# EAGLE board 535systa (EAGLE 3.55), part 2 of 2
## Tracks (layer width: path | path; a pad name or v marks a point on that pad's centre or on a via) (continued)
N$460  (via drill 0.81 pad 1.93)
  other vias: 22.52,77.93
N$461  (via drill 0.81 pad 1.93)
  other vias: 22.52,75.07
N$462  (via drill 0.81 pad 1.93)
  other vias: 22.52,72.21
N$463  (via drill 0.81 pad 1.93)
  other vias: 22.52,69.35
N$464  (via drill 0.81 pad 1.93)
  other vias: 22.52,66.5
N$465  (via drill 0.81 pad 1.93)
  other vias: 22.52,63.64
N$466  (via drill 0.81 pad 1.93)
  other vias: 22.52,60.78
N$467  (via drill 0.81 pad 1.93)
  other vias: 22.52,57.92
N$468  (via drill 0.81 pad 1.93)
  other vias: 22.52,55.07
N$469  (via drill 0.81 pad 1.93)
  other vias: 22.52,52.21
N$470  (via drill 0.81 pad 1.93)
  other vias: 22.52,49.35
N$471  (via drill 0.81 pad 1.93)
  other vias: 22.52,46.49
N$472  (via drill 0.81 pad 1.93)
  other vias: 22.52,43.64
N$473  (via drill 0.81 pad 1.93)
  other vias: 22.52,40.78
N$474  (via drill 0.81 pad 1.93)
  other vias: 22.52,37.92
N$475  (via drill 0.81 pad 1.93)
  other vias: 22.52,35.06
N$476  (via drill 0.81 pad 1.93)
  other vias: 22.52,32.21
N$477  (via drill 0.81 pad 1.93)
  other vias: 22.52,29.35
N$478  (via drill 0.81 pad 1.93)
  other vias: 22.52,26.49
N$479  (via drill 0.81 pad 1.93)
  other vias: 22.52,23.63
N$480  (via drill 0.81 pad 1.93)
  other vias: 22.52,20.78
N$481  (via drill 0.81 pad 1.93)
  other vias: 22.52,17.92
N$482  (via drill 0.81 pad 1.93)
  other vias: 22.52,15.06
N$483  (via drill 0.81 pad 1.93)
  other vias: 22.52,12.2
N$484  (via drill 0.81 pad 1.93)
  other vias: 22.52,9.35
N$485  (via drill 0.81 pad 1.93)
  other vias: 22.52,6.49
N$487  (via drill 0.81 pad 1.93)
  other vias: 19.66,95.07
N$488  (via drill 0.81 pad 1.93)
  other vias: 19.66,92.21
N$489  (via drill 0.81 pad 1.93)
  other vias: 19.66,89.36
N$490  (via drill 0.81 pad 1.93)
  other vias: 19.66,86.5
N$491  (via drill 0.81 pad 1.93)
  other vias: 19.66,83.64
N$492  (via drill 0.81 pad 1.93)
  other vias: 19.66,80.78
N$493  (via drill 0.81 pad 1.93)
  other vias: 19.66,77.93
N$494  (via drill 0.81 pad 1.93)
  other vias: 19.66,75.07
N$495  (via drill 0.81 pad 1.93)
  other vias: 19.66,72.21
N$496  (via drill 0.81 pad 1.93)
  other vias: 19.66,69.35
N$497  (via drill 0.81 pad 1.93)
  other vias: 19.66,66.5
N$498  (via drill 0.81 pad 1.93)
  other vias: 19.66,63.64
N$499  (via drill 0.81 pad 1.93)
  other vias: 19.66,60.78
N$500  (via drill 0.81 pad 1.93)
  other vias: 19.66,57.92
N$501  (via drill 0.81 pad 1.93)
  other vias: 19.66,55.07
N$502  (via drill 0.81 pad 1.93)
  other vias: 19.66,52.21
N$503  (via drill 0.81 pad 1.93)
  other vias: 19.66,49.35
N$504  (via drill 0.81 pad 1.93)
  other vias: 19.66,46.49
N$505  (via drill 0.81 pad 1.93)
  other vias: 19.66,43.64
N$506  (via drill 0.81 pad 1.93)
  other vias: 19.66,40.78
N$507  (via drill 0.81 pad 1.93)
  other vias: 19.66,37.92
N$508  (via drill 0.81 pad 1.93)
  other vias: 19.66,35.06
N$509  (via drill 0.81 pad 1.93)
  other vias: 19.66,32.21
N$510  (via drill 0.81 pad 1.93)
  other vias: 19.66,29.35
N$511  (via drill 0.81 pad 1.93)
  other vias: 19.66,26.49
N$512  (via drill 0.81 pad 1.93)
  other vias: 19.66,23.63
N$513  (via drill 0.81 pad 1.93)
  other vias: 19.66,20.78
N$514  (via drill 0.81 pad 1.93)
  other vias: 19.66,17.92
N$515  (via drill 0.81 pad 1.93)
  other vias: 19.66,15.06
N$516  (via drill 0.81 pad 1.93)
  other vias: 19.66,12.2
N$517  (via drill 0.81 pad 1.93)
  other vias: 19.66,9.35
N$518  (via drill 0.81 pad 1.93)
  other vias: 19.66,6.49
N$520  (via drill 0.81 pad 1.93)
  other vias: 16.8,95.07
N$521  (via drill 0.81 pad 1.93)
  other vias: 16.8,92.21
N$522  (via drill 0.81 pad 1.93)
  other vias: 16.8,89.36
N$523  (via drill 0.81 pad 1.93)
  other vias: 16.8,86.5
N$524  (via drill 0.81 pad 1.93)
  other vias: 16.8,83.64
N$525  (via drill 0.81 pad 1.93)
  other vias: 16.8,80.78
N$526  (via drill 0.81 pad 1.93)
  other vias: 16.8,77.93
N$527  (via drill 0.81 pad 1.93)
  other vias: 16.8,75.07
N$528  (via drill 0.81 pad 1.93)
  other vias: 16.8,72.21
N$529  (via drill 0.81 pad 1.93)
  other vias: 16.8,69.35
N$530  (via drill 0.81 pad 1.93)
  other vias: 16.8,66.5
N$531  (via drill 0.81 pad 1.93)
  other vias: 16.8,63.64
N$532  (via drill 0.81 pad 1.93)
  other vias: 16.8,60.78
N$533  (via drill 0.81 pad 1.93)
  other vias: 16.8,57.92
N$534  (via drill 0.81 pad 1.93)
  other vias: 16.8,55.07
N$535  (via drill 0.81 pad 1.93)
  other vias: 16.8,52.21
N$536  (via drill 0.81 pad 1.93)
  other vias: 16.8,49.35
N$537  (via drill 0.81 pad 1.93)
  other vias: 16.8,46.49
N$538  (via drill 0.81 pad 1.93)
  other vias: 16.8,43.64
N$539  (via drill 0.81 pad 1.93)
  other vias: 16.8,40.78
N$540  (via drill 0.81 pad 1.93)
  other vias: 16.8,37.92
N$541  (via drill 0.81 pad 1.93)
  other vias: 16.8,35.06
N$542  (via drill 0.81 pad 1.93)
  other vias: 16.8,32.21
N$543  (via drill 0.81 pad 1.93)
  other vias: 16.8,29.35
N$544  (via drill 0.81 pad 1.93)
  other vias: 16.8,26.49
N$545  (via drill 0.81 pad 1.93)
  other vias: 16.8,23.63
N$546  (via drill 0.81 pad 1.93)
  other vias: 16.8,20.78
N$547  (via drill 0.81 pad 1.93)
  other vias: 16.8,17.92
N$548  (via drill 0.81 pad 1.93)
  other vias: 16.8,15.06
N$549  (via drill 0.81 pad 1.93)
  other vias: 16.8,12.2
N$550  (via drill 0.81 pad 1.93)
  other vias: 16.8,9.35
N$551  (via drill 0.81 pad 1.93)
  other vias: 16.8,6.49
N$553  (via drill 0.81 pad 1.93)
  other vias: 13.94,95.07
N$554  (via drill 0.81 pad 1.93)
  other vias: 13.94,92.21
N$555  (via drill 0.81 pad 1.93)
  other vias: 13.94,89.36
N$556  (via drill 0.81 pad 1.93)
  other vias: 13.94,86.5
N$557  (via drill 0.81 pad 1.93)
  other vias: 13.94,83.64
N$558  (via drill 0.81 pad 1.93)
  other vias: 13.94,80.78
N$559  (via drill 0.81 pad 1.93)
  other vias: 13.94,77.93
N$560  (via drill 0.81 pad 1.93)
  other vias: 13.94,75.07
N$561  (via drill 0.81 pad 1.93)
  other vias: 13.94,72.21
N$562  (via drill 0.81 pad 1.93)
  other vias: 13.94,69.35
N$563  (via drill 0.81 pad 1.93)
  other vias: 13.94,66.5
N$564  (via drill 0.81 pad 1.93)
  other vias: 13.94,63.64
N$565  (via drill 0.81 pad 1.93)
  other vias: 13.94,60.78
N$566  (via drill 0.81 pad 1.93)
  other vias: 13.94,57.92
N$567  (via drill 0.81 pad 1.93)
  other vias: 13.94,55.07
N$568  (via drill 0.81 pad 1.93)
  other vias: 13.94,52.21
N$569  (via drill 0.81 pad 1.93)
  other vias: 13.94,49.35
N$570  (via drill 0.81 pad 1.93)
  other vias: 13.94,46.49
N$571  (via drill 0.81 pad 1.93)
  other vias: 13.94,43.64
N$572  (via drill 0.81 pad 1.93)
  other vias: 13.94,40.78
N$573  (via drill 0.81 pad 1.93)
  other vias: 13.94,37.92
N$574  (via drill 0.81 pad 1.93)
  other vias: 13.94,35.06
N$575  (via drill 0.81 pad 1.93)
  other vias: 13.94,32.21
N$576  (via drill 0.81 pad 1.93)
  other vias: 13.94,29.35
N$577  (via drill 0.81 pad 1.93)
  other vias: 13.94,26.49
N$578  (via drill 0.81 pad 1.93)
  other vias: 13.94,23.63
N$579  (via drill 0.81 pad 1.93)
  other vias: 13.94,20.78
N$580  (via drill 0.81 pad 1.93)
  other vias: 13.94,17.92
N$581  (via drill 0.81 pad 1.93)
  other vias: 13.94,15.06
N$582  (via drill 0.81 pad 1.93)
  other vias: 13.94,12.2
N$583  (via drill 0.81 pad 1.93)
  other vias: 13.94,9.35
N$584  (via drill 0.81 pad 1.93)
  other vias: 13.94,6.49
N$586  (via drill 0.81 pad 1.93)
  other vias: 11.09,95.07
N$587  (via drill 0.81 pad 1.93)
  other vias: 11.09,92.21
N$588  (via drill 0.81 pad 1.93)
  other vias: 11.09,89.36
N$589  (via drill 0.81 pad 1.93)
  other vias: 11.09,86.5
N$590  (via drill 0.81 pad 1.93)
  other vias: 11.09,83.64
N$591  (via drill 0.81 pad 1.93)
  other vias: 11.09,80.78
N$592  (via drill 0.81 pad 1.93)
  other vias: 11.09,77.93
N$593  (via drill 0.81 pad 1.93)
  other vias: 11.09,75.07
N$594  (via drill 0.81 pad 1.93)
  other vias: 11.09,72.21
N$595  (via drill 0.81 pad 1.93)
  other vias: 11.09,69.35
N$596  (via drill 0.81 pad 1.93)
  other vias: 11.09,66.5
N$597  (via drill 0.81 pad 1.93)
  other vias: 11.09,63.64
N$598  (via drill 0.81 pad 1.93)
  other vias: 11.09,60.78
N$599  (via drill 0.81 pad 1.93)
  other vias: 11.09,57.92
N$600  (via drill 0.81 pad 1.93)
  other vias: 11.09,55.07
N$601  (via drill 0.81 pad 1.93)
  other vias: 11.09,52.21
N$602  (via drill 0.81 pad 1.93)
  other vias: 11.09,49.35
N$603  (via drill 0.81 pad 1.93)
  other vias: 11.09,46.49
N$604  (via drill 0.81 pad 1.93)
  other vias: 11.09,43.64
N$605  (via drill 0.81 pad 1.93)
  other vias: 11.09,40.78
N$606  (via drill 0.81 pad 1.93)
  other vias: 11.09,37.92
N$607  (via drill 0.81 pad 1.93)
  other vias: 11.09,35.06
N$608  (via drill 0.81 pad 1.93)
  other vias: 11.09,32.21
N$609  (via drill 0.81 pad 1.93)
  other vias: 11.09,29.35
N$610  (via drill 0.81 pad 1.93)
  other vias: 11.09,26.49
N$611  (via drill 0.81 pad 1.93)
  other vias: 11.09,23.63
N$612  (via drill 0.81 pad 1.93)
  other vias: 11.09,20.78
N$613  (via drill 0.81 pad 1.93)
  other vias: 11.09,17.92
N$614  (via drill 0.81 pad 1.93)
  other vias: 11.09,15.06
N$615  (via drill 0.81 pad 1.93)
  other vias: 11.09,12.2
N$616  (via drill 0.81 pad 1.93)
  other vias: 11.09,9.35
N$617  (via drill 0.81 pad 1.93)
  other vias: 11.09,6.49
N$619  (via drill 0.81 pad 1.93)
  other vias: 8.23,95.07
N$620  (via drill 0.81 pad 1.93)
  other vias: 8.23,92.21
N$621  (via drill 0.81 pad 1.93)
  other vias: 8.23,89.36
N$622  (via drill 0.81 pad 1.93)
  other vias: 8.23,86.5
N$623  (via drill 0.81 pad 1.93)
  other vias: 8.23,83.64
N$624  (via drill 0.81 pad 1.93)
  other vias: 8.23,80.78
N$625  (via drill 0.81 pad 1.93)
  other vias: 8.23,77.93
N$626  (via drill 0.81 pad 1.93)
  other vias: 8.23,75.07
N$627  (via drill 0.81 pad 1.93)
  other vias: 8.23,72.21
N$628  (via drill 0.81 pad 1.93)
  other vias: 8.23,69.35
N$629  (via drill 0.81 pad 1.93)
  other vias: 8.23,66.5
N$630  (via drill 0.81 pad 1.93)
  other vias: 8.23,63.64
N$631  (via drill 0.81 pad 1.93)
  other vias: 8.23,60.78
N$632  (via drill 0.81 pad 1.93)
  other vias: 8.23,57.92
N$633  (via drill 0.81 pad 1.93)
  other vias: 8.23,55.07
N$634  (via drill 0.81 pad 1.93)
  other vias: 8.23,52.21
N$635  (via drill 0.81 pad 1.93)
  other vias: 8.23,49.35
N$636  (via drill 0.81 pad 1.93)
  other vias: 8.23,46.49
N$637  (via drill 0.81 pad 1.93)
  other vias: 8.23,43.64
N$638  (via drill 0.81 pad 1.93)
  other vias: 8.23,40.78
N$639  (via drill 0.81 pad 1.93)
  other vias: 8.23,37.92
N$640  (via drill 0.81 pad 1.93)
  other vias: 8.23,35.06
N$641  (via drill 0.81 pad 1.93)
  other vias: 8.23,32.21
N$642  (via drill 0.81 pad 1.93)
  other vias: 8.23,29.35
N$643  (via drill 0.81 pad 1.93)
  other vias: 8.23,26.49
N$644  (via drill 0.81 pad 1.93)
  other vias: 8.23,23.63
N$645  (via drill 0.81 pad 1.93)
  other vias: 8.23,20.78
N$646  (via drill 0.81 pad 1.93)
  other vias: 8.23,17.92
N$647  (via drill 0.81 pad 1.93)
  other vias: 8.23,15.06
N$648  (via drill 0.81 pad 1.93)
  other vias: 8.23,12.2
N$649  (via drill 0.81 pad 1.93)
  other vias: 8.23,9.35
N$650  (via drill 0.81 pad 1.93)
  other vias: 8.23,6.49
N$652  (via drill 0.81 pad 1.93)
  other vias: 5.05,95.07
N$653  (via drill 0.81 pad 1.93)
  other vias: 5.05,92.21
N$654  (via drill 0.81 pad 1.93)
  other vias: 5.05,89.36
N$655  (via drill 0.81 pad 1.93)
  other vias: 5.05,86.5
N$656  (via drill 0.81 pad 1.93)
  other vias: 5.05,83.64
N$657  (via drill 0.81 pad 1.93)
  other vias: 5.05,80.78
N$658  (via drill 0.81 pad 1.93)
  other vias: 5.05,77.93
N$659  (via drill 0.81 pad 1.93)
  other vias: 5.05,75.07
N$660  (via drill 0.81 pad 1.93)
  other vias: 5.05,72.21
N$661  (via drill 0.81 pad 1.93)
  other vias: 5.05,69.35
N$662  (via drill 0.81 pad 1.93)
  other vias: 5.05,66.5
N$663  (via drill 0.81 pad 1.93)
  other vias: 5.05,63.64
N$664  (via drill 0.81 pad 1.93)
  other vias: 5.05,60.78
N$665  (via drill 0.81 pad 1.93)
  other vias: 5.05,57.92
N$666  (via drill 0.81 pad 1.93)
  other vias: 5.05,55.07
N$667  (via drill 0.81 pad 1.93)
  other vias: 5.05,52.21
N$668  (via drill 0.81 pad 1.93)
  other vias: 5.05,49.35
N$669  (via drill 0.81 pad 1.93)
  other vias: 5.05,46.49
N$670  (via drill 0.81 pad 1.93)
  other vias: 5.05,43.64
N$671  (via drill 0.81 pad 1.93)
  other vias: 5.05,40.78
N$672  (via drill 0.81 pad 1.93)
  other vias: 5.05,37.92
N$673  (via drill 0.81 pad 1.93)
  other vias: 5.05,35.06
N$674  (via drill 0.81 pad 1.93)
  other vias: 5.05,32.21
N$675  (via drill 0.81 pad 1.93)
  other vias: 5.05,29.35
N$676  (via drill 0.81 pad 1.93)
  other vias: 5.05,26.49
N$677  (via drill 0.81 pad 1.93)
  other vias: 5.05,23.63
N$678  (via drill 0.81 pad 1.93)
  other vias: 5.05,20.78
N$679  (via drill 0.81 pad 1.93)
  other vias: 5.05,17.92
N$680  (via drill 0.81 pad 1.93)
  other vias: 5.05,15.06
N$681  (via drill 0.81 pad 1.93)
  other vias: 5.05,12.2
N$682  (via drill 0.81 pad 1.93)
  other vias: 5.05,9.35
N$683  (via drill 0.81 pad 1.93)
  other vias: 5.05,6.49
N$705  (via drill 0.81 pad 1.93)
  other vias: 1.88,6.49
N$706  (via drill 0.81 pad 1.93)
  other vias: 1.88,9.35
N$707  (via drill 0.81 pad 1.93)
  other vias: 1.88,12.2
N$708  (via drill 0.81 pad 1.93)
  other vias: 1.88,15.06
N$709  (via drill 0.81 pad 1.93)
  other vias: 1.88,17.92
N$710  (via drill 0.81 pad 1.93)
  other vias: 1.88,20.78
N$711  (via drill 0.81 pad 1.93)
  other vias: 1.88,23.63
N$712  (via drill 0.81 pad 1.93)
  other vias: 1.88,26.49
N$713  (via drill 0.81 pad 1.93)
  other vias: 1.88,29.35
N$714  (via drill 0.81 pad 1.93)
  other vias: 1.88,32.21
N$715  (via drill 0.81 pad 1.93)
  other vias: 1.88,35.06
N$716  (via drill 0.81 pad 1.93)
  other vias: 1.88,37.92
N$717  (via drill 0.81 pad 1.93)
  other vias: 1.88,40.78
N$718  (via drill 0.81 pad 1.93)
  other vias: 1.88,43.64
N$719  (via drill 0.81 pad 1.93)
  other vias: 1.88,46.49
N$720  (via drill 0.81 pad 1.93)
  other vias: 1.88,49.35
N$721  (via drill 0.81 pad 1.93)
  other vias: 1.88,52.21
N$722  (via drill 0.81 pad 1.93)
  other vias: 1.88,55.07
N$723  (via drill 0.81 pad 1.93)
  other vias: 1.88,57.92
N$724  (via drill 0.81 pad 1.93)
  other vias: 1.88,60.78
N$725  (via drill 0.81 pad 1.93)
  other vias: 1.88,63.64
N$726  (via drill 0.81 pad 1.93)
  other vias: 1.88,66.5
N$727  (via drill 0.81 pad 1.93)
  other vias: 1.88,69.35
N$728  (via drill 0.81 pad 1.93)
  other vias: 1.88,72.21
N$729  (via drill 0.81 pad 1.93)
  other vias: 1.88,75.07
N$730  (via drill 0.81 pad 1.93)
  other vias: 1.88,77.93
N$731  (via drill 0.81 pad 1.93)
  other vias: 1.88,80.78
N$732  (via drill 0.81 pad 1.93)
  other vias: 1.88,83.64
N$733  (via drill 0.81 pad 1.93)
  other vias: 1.88,86.5
N$734  (via drill 0.81 pad 1.93)
  other vias: 1.88,89.36
N$735  (via drill 0.81 pad 1.93)
  other vias: 1.88,92.21
P00  (via drill 0.61 pad 1.02)
  Top 0.254: 101.57,75.71 101.26,76.02 101.26,76.97 100.62,77.61 100.62,81.42 101.26,82.05 101.89,82.05 102.53,82.69 v102.53,84.28 102.53,87.77 102.21,88.09 v102.21,96.34 | 135.86,4.27 135.86,16.97 134.91,17.92 134.91,21.09 135.86,22.05 135.86,24.27 134.91,25.22 134.91,38.87 135.86,39.83 | v74.27,5.85 74.27,16.33 73.63,16.97 72.36,16.97 | v101.26,6.49 v101.26,8.4 | v127.61,41.42 127.29,41.73 127.29,56.65 127.93,57.29 127.93,70.63 128.88,71.58 128.88,84.91 128.24,85.55 IC10.4
  Bottom 0.254: v102.53,84.28 125.07,84.28 126.34,85.55 IC10.4 | v102.21,96.34 66.01,96.34 65.38,95.71 U$1. | v74.27,5.85 74.59,5.54 96.49,5.54 97.76,6.81 100.94,6.81 v101.26,6.49 | v101.26,8.4 101.57,8.08 135.23,8.08 135.86,7.44 135.86,4.27 | v127.61,41.42 131.42,41.42 132.05,40.78 132.05,39.51 132.69,38.87 134.91,38.87 135.86,39.83
P01  (via drill 0.61 pad 1.02)
  Top 0.254: 99.03,75.71 98.08,75.71 97.45,76.34 v97.45,86.82 v97.45,97.3 | 138.4,4.27 138.4,16.97 137.45,17.92 137.45,21.09 138.4,22.05 138.4,24.27 137.45,25.22 137.45,39.83 | 137.45,39.83 138.4,39.83 | v75.54,8.08 v75.54,19.51 | v138.09,86.82 138.4,86.5 138.4,63.32 137.45,62.37 137.45,39.83
  Bottom 0.254: v97.45,86.82 126.34,86.82 126.97,87.45 | v97.45,97.3 62.84,97.3 62.2,96.66 U$2. | v75.54,8.08 99.03,8.08 99.67,7.44 104.75,7.44 105.38,6.81 133.96,6.81 134.59,6.17 134.59,3.95 135.23,3.31 137.45,3.31 138.4,4.27 | v75.54,19.51 72.36,19.51 | 126.97,87.45 127.61,86.82 v138.09,86.82 | 126.97,87.45 IC10.3
P02  (via drill 0.61 pad 1.02)
  Top 0.254: 101.57,78.24 103.48,80.15 103.48,84.91 103.16,85.23 v103.16,89.36 v103.16,94.12 | 140.94,4.27 v140.94,10.62 140.94,16.97 139.99,17.92 139.99,21.09 140.94,22.05 140.94,24.91 140.63,25.22 140.63,34.43 139.99,35.07 139.99,39.51 140.31,39.83 | 140.31,39.83 140.94,39.83 | v85.7,22.05 v85.7,10.62 | v139.99,89.36 139.99,49.35 140.31,49.04 140.31,39.83
  Bottom 0.254: v103.16,89.36 126.34,89.36 126.97,89.99 | v103.16,94.12 102.84,94.44 67.6,94.44 U$3. | v85.7,10.62 88.24,10.62 89.51,9.35 97.76,9.35 99.03,10.62 v140.94,10.62 | 72.36,22.05 v85.7,22.05 | 126.97,89.99 127.61,89.36 v139.99,89.36 | 126.97,89.99 IC10.2
P03  (via drill 0.61 pad 1.02)
  Top 0.254: v100.62,91.58 100.62,87.45 99.99,86.82 98.72,86.82 98.08,86.18 98.08,78.88 98.72,78.24 99.03,78.24 | v64.11,87.77 64.11,89.99 63.47,90.63 U$4. | 143.48,19.51 144.44,20.46 144.44,34.11 143.48,35.07 143.48,37.29 144.44,38.24 144.44,40.15 144.12,40.46 144.12,48.72 143.48,49.35 143.48,55.07 | v129.2,56.65 129.51,56.97 129.51,92.53 128.88,93.17 IC10.1
  Bottom 0.254: IC10.1 126.97,92.53 126.34,91.9 115.54,91.9 115.23,91.58 v100.62,91.58 90.78,91.58 90.14,90.94 90.14,87.77 89.51,87.13 88.24,87.13 87.6,87.77 87.6,88.72 86.97,89.36 76.49,89.36 76.17,89.04 69.51,89.04 68.55,88.09 64.43,88.09 v64.11,87.77 | 142.53,19.51 142.53,9.98 141.9,9.35 105.38,9.35 | 142.53,19.51 142.53,24.91 141.9,25.54 107.61,25.54 107.29,25.86 97.13,25.86 96.49,25.22 96.49,23.95 95.86,23.32 93.95,23.32 93.32,23.95 93.32,25.22 92.68,25.86 86.65,25.86 86.02,25.22 73,25.22 72.36,24.59 | 142.53,19.51 143.48,19.51 | v129.2,56.65 142.85,56.65 143.48,56.02 143.48,55.07
P04  (via drill 0.61 pad 1.02)
  Top 0.254: v90.14,81.74 v90.14,84.28 | v70.78,85.23 70.78,94.75 70.14,95.39 67.6,95.39 66.97,94.75 66.97,90.31 66.01,89.36 U$5. | v81.57,27.13 v81.57,18.24 | 140.94,19.51 141.26,19.82 141.26,21.09 141.9,21.73 141.9,23.32 141.58,23.63 141.58,34.75 140.94,35.38 140.94,37.29 140.94,38.24 141.9,39.19 141.9,40.78 140.94,41.73 140.94,55.07 | v111.42,80.79 111.73,80.47 v111.73,64.59 | v116.18,64.59 116.18,63.64 118.08,61.74 v118.08,56.65
  Bottom 0.254: v90.14,81.74 100.62,81.74 101.57,80.79 v111.42,80.79 | v90.14,84.28 80.94,84.28 80.3,84.91 71.09,84.91 v70.78,85.23 | v81.57,18.24 93.95,18.24 95.22,16.97 97.76,16.97 100.62,16.97 101.89,15.7 106.65,15.7 107.29,16.33 140.31,16.33 140.94,16.97 140.94,19.51 | 72.36,27.13 v81.57,27.13 | v116.18,64.59 v111.73,64.59 | v118.08,56.65 127.93,56.65 128.88,55.7 129.83,55.7 130.15,56.02 140.31,56.02 140.94,55.39 140.94,55.07
P05  (via drill 0.61 pad 1.02)
  Top 0.254: v72.36,79.83 v72.36,89.99 | 138.4,19.51 139.36,20.46 139.36,34.11 138.4,35.07 138.4,37.29 138.4,38.24 139.36,39.19 139.36,40.78 138.4,41.73 138.4,55.07 | v102.53,30.62 102.53,20.78 104.43,18.87 104.43,17.6 105.07,16.97 105.38,16.97 | v89.19,80.79 89.83,80.15 89.83,54.43 89.19,53.8 89.19,34.11 88.87,33.79 v88.87,30.94
  Bottom 0.254: v72.36,79.83 72.68,80.15 74.59,80.15 74.9,79.83 81.57,79.83 82.52,80.79 v89.19,80.79 99.03,80.79 | v72.36,89.99 67.92,89.99 67.28,90.63 64.43,90.63 63.16,89.36 63.16,88.72 U$6. | v102.53,30.62 89.51,30.62 89.19,30.94 v88.87,30.94 78.71,30.94 77.44,29.67 72.36,29.67 | 138.4,19.51 138.4,17.6 137.77,16.97 105.38,16.97
P06  (via drill 0.61 pad 1.02)
  Top 0.254: 135.86,19.51 136.82,20.46 136.82,34.11 135.86,35.07 135.86,37.29 135.86,38.24 136.82,39.19 136.82,40.78 135.86,41.73 135.86,55.07 v135.86,70.94 | v106.02,70.94 v106.02,83.33 | v82.84,33.48 82.84,48.4 83.16,48.72 83.16,54.75 82.84,55.07 v82.84,69.99 82.84,96.34 82.21,96.98 77.76,96.98 77.13,96.34 v77.13,87.45 | v107.61,18.24 108.24,18.87 v108.24,24.27
  Bottom 0.254: v135.86,70.94 v106.02,70.94 105.7,70.63 105.7,69.99 105.38,69.67 90.14,69.67 89.83,69.99 v82.84,69.99 | v106.02,83.33 101.57,83.33 | v82.84,33.48 79.03,33.48 77.76,32.21 72.36,32.21 | v107.61,18.24 104.75,18.24 103.48,19.51 97.76,19.51 | v108.24,24.27 133.96,24.27 134.59,23.63 134.59,20.14 135.23,19.51 135.86,19.51 | v77.13,87.45 74.59,87.45 74.27,87.13 66.01,87.13 U$7.
P07  (via drill 0.61 pad 1.02)
  Top 0.254: 133.32,19.51 134.28,20.46 134.28,34.11 133.32,35.07 133.32,37.29 133.32,38.24 134.28,39.19 134.28,40.78 133.32,41.73 133.32,55.07 v133.32,58.24 | v83.79,34.75 v83.79,20.78 | v122.53,58.24 v122.53,81.74
  Bottom 0.254: U$8. 68.24,84.91 68.87,84.28 79.35,84.28 80.3,83.33 99.03,83.33 99.99,82.37 103.16,82.37 103.8,81.74 v122.53,81.74 | v83.79,20.78 104.75,20.78 105.38,20.14 105.38,19.51 108.24,19.51 109.83,17.92 132.69,17.92 133.32,18.56 133.32,19.51 | 72.36,34.75 v83.79,34.75 | v133.32,58.24 v122.53,58.24
P10  (via drill 0.61 pad 1.02)
  Top 0.254: v86.65,50.94 87.92,52.21 87.92,64.91 88.56,65.55 88.87,65.55
  Bottom 0.254: v86.65,50.94 74.9,50.94 74.59,51.26 69.51,51.26 67.6,49.35 U$9.
P11  (via drill 0.61 pad 1.02)
  Top 0.254: v68.87,48.4 68.87,57.29 69.51,57.93 v69.51,58.88
  Bottom 0.254: v69.51,58.88 88.24,58.88 88.87,59.51 88.87,63 | v68.87,48.4 66.65,48.4 66.01,47.76 U$10.
P12  (via drill 0.61 pad 1.02)
  Top 0.254: v70.46,60.15 70.46,57.61 69.51,56.65 69.51,49.04 69.82,48.72 69.82,46.81 v69.51,46.5
  Bottom 0.254: v70.46,60.15 86.97,60.15 87.6,60.78 87.6,64.28 86.33,65.55 | U$11. v69.51,46.5
P13  (via drill 0.61 pad 1.02)
  Top 0.254: v85.7,46.5 85.7,53.8 86.33,54.43 86.33,63
  Bottom 0.254: v85.7,46.5 85.38,46.18 71.41,46.18 70.78,45.54 66.65,45.54 66.01,44.91 U$12.
P14  (via drill 0.61 pad 1.02)
  Top 0.254: v71.41,61.1 69.82,61.1 67.92,59.19 67.92,56.97 68.24,56.65 68.24,50.62 67.92,50.3 67.92,48.08 68.24,47.76 v68.24,43.96
  Bottom 0.254: 83.79,65.55 85.06,64.28 85.06,61.42 84.43,60.78 73.32,60.78 73,61.1 v71.41,61.1 | v68.24,43.96 67.92,43.64 U$13.
P15  (via drill 0.61 pad 1.02)
  Top 0.254: v76.49,51.89 v76.49,61.74 | v67.28,51.89 67.28,48.72 66.65,48.08 64.43,48.08 63.79,47.45 63.79,43.64 U$14.
  Bottom 0.254: v76.49,61.74 82.52,61.74 83.79,63 | v67.28,51.89 v76.49,51.89
P16  (via drill 0.61 pad 1.02)
  Top 0.254: v72.36,64.59 72.36,56.02 71.73,55.39 70.78,55.39 70.14,54.75 70.14,49.35 70.46,49.04 70.46,41.1 v70.14,40.78
  Bottom 0.254: v72.36,64.59 79.35,64.59 80.3,65.55 81.25,65.55 | U$15. v70.14,40.78
P17  (via drill 0.61 pad 1.02)
  Top 0.254: v81.57,72.53 81.57,68.72 82.21,68.08 82.21,63.96 81.25,63 | v113.96,73.8 114.27,73.48 v114.27,69.99 | v144.75,69.99 144.75,40.78 145.07,40.46 v145.07,3.31 | v69.19,5.85 v69.19,22.36 | v63.47,23.32 63.47,37.92 U$16.
  Bottom 0.254: v81.57,72.53 83.16,74.12 105.38,74.12 | 105.38,74.12 105.7,74.12 | 105.38,74.12 113.64,74.12 v113.96,73.8 | v114.27,69.99 114.59,70.31 117.13,70.31 117.45,69.99 v144.75,69.99 | v145.07,3.31 142.21,3.31 140.94,2.04 107.92,2.04 106.97,3 75.54,3 73,5.54 72.05,5.54 71.41,6.17 69.51,6.17 v69.19,5.85 | v69.19,22.36 64.43,22.36 v63.47,23.32
P40  (via drill 0.61 pad 1.02)
  Top 0.254: v74.59,83.33 v74.59,89.99
  Bottom 0.254: v74.59,89.99 88.24,89.99 88.87,89.36 88.87,88.41 | v74.59,83.33 74.27,83.64 U$17.
P41  (via drill 0.61 pad 1.02)
  Top 0.254: v88.87,82.37 88.87,85.86
  Bottom 0.254: v88.87,82.37 73,82.37 72.68,82.69 68.24,82.69 67.6,82.05 U$18.
P42  (via drill 0.61 pad 1.02)
  Top 0.254: v68.87,80.79 v68.87,90.94 | v86.33,90.94 86.33,88.41
  Bottom 0.254: v86.33,90.94 86.02,90.63 77.44,90.63 77.13,90.94 v68.87,90.94 | U$19. v68.87,80.79
P43  (via drill 0.61 pad 1.02)
  Top 0.254: v67.92,91.9 67.92,89.04 68.24,88.72 68.24,83.96 67.92,83.64 v67.92,79.2 | v83.79,91.58 83.79,88.41
  Bottom 0.254: v83.79,91.58 77.76,91.58 77.44,91.9 v67.92,91.9 | U$20. v67.92,79.2
P44  (via drill 0.61 pad 1.02)
  Top 0.254: v83.79,77.29 83.79,85.86
  Bottom 0.254: v83.79,77.29 66.01,77.29 U$21.
P45  (via drill 0.61 pad 1.02)
  Top 0.254: v67.28,86.18 67.28,80.15 66.65,79.52 64.74,79.52 62.2,76.97 U$22.
  Bottom 0.254: v67.28,86.18 74.59,86.18 75.22,86.82 76.49,86.82 76.81,86.5 77.76,86.5 78.08,86.82 80.62,86.82 81.25,87.45 81.25,88.41
P46  (via drill 0.61 pad 1.02)
  Top 0.254: v81.25,76.34 81.25,85.86
  Bottom 0.254: v81.25,76.34 80.94,76.66 66.97,76.66 U$23.
P47  (via drill 0.61 pad 1.02)
  Top 0.254: v73.63,88.09 73.63,82.05 74.59,81.1 v74.59,75.07 | v67.28,75.07 65.7,73.48 U$24.
  Bottom 0.254: v73.63,88.09 73.95,88.41 78.71,88.41 | v67.28,75.07 v74.59,75.07
P50  (via drill 0.61 pad 1.02)
  Top 0.254: v92.37,67.13 92.37,87.77 91.73,88.41 91.41,88.41 | v73.63,62.05 v73.63,66.18
  Bottom 0.254: v92.37,67.13 91.73,66.5 73.95,66.5 v73.63,66.18 | v73.63,62.05 67.6,62.05 66.33,60.78 U$25.
P51  (via drill 0.61 pad 1.02)
  Top 0.254: v75.86,69.35 74.59,68.08 v74.59,57.93 | v93.95,70.63 93.95,85.86
  Bottom 0.254: v93.95,70.63 93.64,70.94 81.57,70.94 80.3,69.67 76.17,69.67 v75.86,69.35 | v74.59,57.93 68.24,57.93 66.97,59.19 U$26.
P52  (via drill 0.61 pad 1.02)
  Top 0.254: v94.91,71.58 94.59,71.9 94.59,84.91 94.91,85.23 94.91,87.77 94.27,88.41 93.95,88.41 | v77.44,71.58 77.13,71.26 77.13,64.28 75.54,62.69 75.54,57.29 v74.9,56.65
  Bottom 0.254: v77.44,71.58 v94.91,71.58 | v74.9,56.65 74.59,56.97 66.33,56.97 U$27.
P53  (via drill 0.61 pad 1.02)
  Top 0.254: v97.45,59.83 97.45,69.67 96.49,70.63 96.49,85.86
  Bottom 0.254: v97.45,59.83 90.46,59.83 88.87,58.24 77.44,58.24 76.81,57.61 76.81,56.34 76.17,55.7 68.87,55.7 68.24,56.34 U$28.
P54  (via drill 0.61 pad 1.02)
  Top 0.254: v100.3,93.49 100.3,97.93 99.67,98.57 97.13,98.57 96.49,97.93 96.49,88.41 | v121.26,93.17 120.94,92.85 120.94,60.15 119.67,58.88 v119.67,53.48 | v112.05,53.48 112.05,38.87 111.42,38.24 111.42,31.25 v112.05,30.62 | v104.43,30.62 104.11,30.3 104.11,28.72 v104.43,28.4 | v93.64,33.79 v93.64,29.35 | v84.75,55.07 v84.75,33.48
  Bottom 0.254: v100.3,93.49 100.62,93.17 108.24,93.17 109.51,94.44 117.77,94.44 118.72,93.49 120.94,93.49 v121.26,93.17 | v112.05,53.48 v119.67,53.48 | v104.43,30.62 v112.05,30.62 | v104.43,28.4 104.11,28.08 97.13,28.08 95.86,29.35 v93.64,29.35 | v93.64,33.79 89.19,33.79 88.87,33.48 v84.75,33.48 | U$29. v84.75,55.07
P55  (via drill 0.61 pad 1.02)
  Top 0.254: v95.54,84.28 95.86,83.96 95.86,70.63 94.27,69.04 v94.27,68.08 | v67.28,67.45 67.28,63.64 65.7,62.05 64.74,62.05 64.11,61.42 v64.11,50.94
  Bottom 0.254: v95.54,84.28 97.45,84.28 99.03,85.86 | v94.27,68.08 91.41,68.08 90.46,67.13 67.6,67.13 v67.28,67.45 | v64.11,50.94 64.11,52.85 63.47,53.48 U$30.
P56  (via drill 0.61 pad 1.02)
  Top 0.254: v69.82,93.49 69.82,82.37 69.51,82.05 69.51,81.42 69.82,81.1 69.82,67.77 68.24,66.18 68.24,60.47 66.97,59.19 66.97,53.8 U$31. | v99.03,93.49 99.03,88.41
  Bottom 0.254: v69.82,93.49 v99.03,93.49
P57  (via drill 0.61 pad 1.02)
  Top 0.254: v99.99,76.66 99.99,85.23 100.62,85.86 101.57,85.86 | v64.11,70.63 63.47,69.99 63.47,51.89 U$32.
  Bottom 0.254: v99.99,76.66 89.83,76.66 88.56,75.39 80.62,75.39 79.35,74.12 78.4,74.12 76.49,72.21 71.41,72.21 69.82,70.63 v64.11,70.63
P60
  Bottom 0.254: 76.17,73.16 66.33,73.16 U$33.
P61
  Bottom 0.254: 78.71,75.71 77.44,74.44 75.86,74.44 75.22,73.8 64.43,73.8 63.47,72.85 63.47,71.9 U$34.
P62  (via drill 0.61 pad 1.02)
  Top 0.254: v74.59,69.35 74.59,73.48 76.17,75.07 76.17,75.71
  Bottom 0.254: U$35. v74.59,69.35
P63  (via drill 0.61 pad 1.02)
  Top 0.254: v73.63,68.4 v73.63,79.2
  Bottom 0.254: v73.63,79.2 77.76,79.2 78.71,78.24 | v73.63,68.4 66.33,68.4 65.7,67.77 U$36.
P64  (via drill 0.61 pad 1.02)
  Top 0.254: v68.87,78.24 68.24,77.61 68.24,69.67 65.38,66.82 U$37.
  Bottom 0.254: v68.87,78.24 76.17,78.24
P65  (via drill 0.61 pad 1.02)
  Top 0.254: v70.46,81.74 70.46,76.34 71.09,75.71 71.09,67.45 70.46,66.82 v70.46,64.91
  Bottom 0.254: v70.46,81.74 77.76,81.74 78.71,80.79 | U$38. v70.46,64.91
P66  (via drill 0.61 pad 1.02)
  Top 0.254: v71.41,80.79 71.41,78.24 71.73,77.93 71.73,66.18 71.41,65.86 v71.41,63.64
  Bottom 0.254: v71.41,80.79 76.17,80.79 | U$39. v71.41,63.64
P67  (via drill 0.61 pad 1.02)
  Top 0.254: v80.3,63.96 80.3,82.69 79.67,83.33 78.71,83.33
  Bottom 0.254: v80.3,63.96 73.95,63.96 72.68,62.69 66.33,62.69 65.7,62.05 U$40.
PA0  (via drill 0.61 pad 1.02)
  Top 0.254: v84.75,15.06 84.75,9.98 85.38,9.35 87.6,9.35
  Bottom 0.254: v84.75,15.06 84.11,15.7 71.09,15.7 70.46,15.06 U$41.
PA1  (via drill 0.61 pad 1.02)
  Top 0.254: v64.11,8.08 63.47,8.71 63.47,12.84 62.84,13.48 U$42.
  Bottom 0.254: v64.11,8.08 73.32,8.08 74.59,6.81 87.6,6.81
PA2  (via drill 0.61 pad 1.02)
  Top 0.254: v76.49,13.16 v76.49,4.27
  Bottom 0.254: v76.49,13.16 66.33,13.16 U$43. | v76.49,4.27 87.6,4.27
PA3  (via drill 0.61 pad 1.02)
  Top 0.254: v83.79,10.62 83.79,2.36 84.43,1.73 87.6,1.73
  Bottom 0.254: U$44. v83.79,10.62
PA4
  Top 0.254: IC6. 67.28,1.73 66.65,2.36 66.65,8.71 66.01,9.35 U$45.
PA5  (via drill 0.61 pad 1.02)
  Top 0.254: v64.11,4.27 64.11,5.85 U$46.
  Bottom 0.254: v64.11,4.27 72.36,4.27
PA6
  Bottom 0.254: 72.36,6.81 66.01,6.81 65.7,6.49 U$47.
PA7  (via drill 0.61 pad 1.02)
  Top 0.254: v70.46,5.22 70.46,8.71 71.09,9.35 72.36,9.35
  Bottom 0.254: v70.46,5.22 70.14,4.9 68.55,4.9 68.24,5.22 62.52,5.22 U$48.
PB0
  Bottom 0.254: 87.6,44.91 89.51,43 89.51,39.19 88.87,38.56 66.01,38.56 U$49.
PB1  (via drill 0.61 pad 1.02)
  Top 0.254: v85.7,36.02 85.7,44.91 87.6,46.81 87.6,47.45
  Bottom 0.254: v85.7,36.02 71.73,36.02 71.41,36.33 U$50.
PB2  (via drill 0.61 pad 1.02)
  Top 0.254: v77.13,40.78 v77.13,49.99 | v73.32,40.78 73.63,40.46 73.63,36.65 73,36.02 71.41,36.02 v70.46,35.07
  Bottom 0.254: v73.32,40.78 v77.13,40.78 | v77.13,49.99 87.6,49.99 | U$51. v70.46,35.07
PB3  (via drill 0.61 pad 1.02)
  Top 0.254: v75.22,33.48 75.22,49.35 74.59,49.99 72.36,49.99
  Bottom 0.254: U$52. v75.22,33.48
PB4  (via drill 0.61 pad 1.02)
  Top 0.254: v67.28,47.45 67.28,39.19 68.55,37.92 68.55,36.65 67.28,35.38 67.28,33.16 66.33,32.21 U$53.
  Bottom 0.254: v67.28,47.45 72.36,47.45
PB5  (via drill 0.61 pad 1.02)
  Top 0.254: v74.27,30.94 74.27,44.27 73.63,44.91 72.36,44.91
  Bottom 0.254: U$54. 67.28,30.62 67.6,30.94 v74.27,30.94
PB6  (via drill 0.61 pad 1.02)
  Top 0.254: v69.19,42.37 69.19,40.46 69.82,39.83 69.82,36.02 69.19,35.38 69.19,29.35 68.55,28.72 67.28,28.72 66.65,29.35 U$55.
  Bottom 0.254: v69.19,42.37 72.36,42.37
PB7  (via drill 0.61 pad 1.02)
  Top 0.254: v68.24,29.67 68.24,35.38 69.19,36.33 69.19,38.87 v68.24,39.83
  Bottom 0.254: v68.24,39.83 72.36,39.83 | U$56. 67.6,27.76 68.24,28.4 v68.24,29.67
PC0  (via drill 0.61 pad 1.02)
  Top 0.254: v85.7,28.08 85.7,34.11 86.33,34.75 87.6,34.75
  Bottom 0.254: v85.7,28.08 85.7,26.49 85.06,25.86 72.05,25.86 71.41,26.49 U$57.
PC1  (via drill 0.61 pad 1.02)
  Top 0.254: v76.17,37.29 76.17,26.49 75.54,25.86 71.73,25.86 v71.09,25.22
  Bottom 0.254: v71.09,25.22 70.78,24.91 U$58. | v76.17,37.29 87.6,37.29
PC2  (via drill 0.61 pad 1.02)
  Top 0.254: U$59. 64.74,23.63 64.11,24.27 v64.11,42.05
  Bottom 0.254: v64.11,42.05 67.6,42.05 69.19,43.64 78.08,43.64 78.71,43 78.71,40.46 79.35,39.83 87.6,39.83
PC3  (via drill 0.61 pad 1.02)
  Top 0.254: v80.62,42.37 80.3,42.05 80.3,16.65 80.94,16.01 80.94,3.63 80.3,3 68.87,3 68.24,3.63 68.24,15.7 67.28,16.65 67.28,21.41 66.65,22.05 U$60.
  Bottom 0.254: v80.62,42.37 87.6,42.37
PC4  (via drill 0.61 pad 1.02)
  Top 0.254: v82.52,20.78 v82.52,32.21
  Bottom 0.254: v82.52,32.21 87.6,32.21 | U$61. v82.52,20.78
PC5  (via drill 0.61 pad 1.02)
  Top 0.254: v70.14,19.19 v70.14,28.4
  Bottom 0.254: v70.14,28.4 78.08,28.4 78.71,29.03 86.97,29.03 87.6,29.67 | U$62. v70.14,19.19
PC6  (via drill 0.61 pad 1.02)
  Top 0.254: v84.75,19.19 84.75,26.49 85.38,27.13 87.6,27.13
  Bottom 0.254: v84.75,19.19 79.03,19.19 78.08,18.24 71.73,18.24 71.41,17.92 U$63.
PC7  (via drill 0.61 pad 1.02)
  Top 0.254: v68.24,16.97 v68.24,23.32
  Bottom 0.254: v68.24,23.32 86.33,23.32 87.6,24.59 | U$64. 67.92,16.33 68.24,16.65 v68.24,16.97
PSEN  (via drill 0.61 pad 1.02)
  Top 0.254: v99.99,67.13 99.99,69.99 99.35,70.63 99.03,70.63 | v125.7,67.77 125.7,55.07 v125.7,45.54 | v101.26,31.89 101.57,32.21 v101.57,45.86
  Bottom 0.254: v99.99,67.13 103.48,67.13 104.11,67.77 v125.7,67.77 | v101.57,45.86 125.39,45.86 v125.7,45.54 | 97.76,31.89 v101.26,31.89
PWR  (via drill 0.61 pad 1.02)
  Top 0.254: 116.81,85.55 118.72,85.55 119.35,86.18 119.35,97.93 119.99,98.57 126.34,98.57 126.97,97.93 IC10.0 | v108.88,38.24 108.88,58.56 109.19,58.88 | v104.11,85.55 104.11,75.71 103.8,75.39 103.8,59.51 v104.11,59.19
  Bottom 0.254: v108.88,38.24 112.05,38.24 113,37.29 | v104.11,59.19 104.43,58.88 109.19,58.88 | v104.11,85.55 116.81,85.55
RD  (via drill 0.61 pad 1.02)
  Top 0.254: 78.71,65.55 79.03,65.23 79.03,63.96 79.67,63.32 79.67,59.19 80.3,58.56 81.57,58.56 82.21,57.93 v82.21,51.89 81.57,51.26 80.3,51.26 79.67,50.62 v79.67,11.89 | v129.2,52.53 129.2,55.07 130.15,56.02 130.15,92.53 130.78,93.17 134.59,93.17
  Bottom 0.254: v82.21,51.89 94.91,51.89 | 94.91,51.89 94.91,51.57 96.81,49.67 97.76,49.67 | v79.67,11.89 87.6,11.89 | v129.2,52.53 109.83,52.53 108.88,53.48 96.18,53.48 94.91,52.21 94.91,51.89
RESET  (via drill 0.61 pad 1.02)
  Top 0.254: v76.17,98.25 76.17,85.86 | 122.53,94.44 122.53,96.34 C9. | 122.53,94.44 122.53,84.91 123.16,84.28 126.34,84.28 126.97,83.64 IC10.5 | v145.71,67.77 v145.71,41.1 | v103.16,77.93 v103.16,54.75 103.48,54.43 v103.48,23.32 | 122.53,94.44 120.62,94.44 119.99,93.8 119.99,78.56 119.35,77.93 116.81,77.93
  Bottom 0.254: v76.17,98.25 121.89,98.25 C9. | v145.71,41.1 148.56,41.1 | 151.1,67.77 v145.71,67.77 145.71,70.63 145.07,71.26 137.77,71.26 137.13,71.9 137.13,74.12 137.13,76.02 136.5,76.66 132.37,76.66 129.83,79.2 122.21,79.2 120.94,77.93 116.81,77.93 v103.16,77.93 | v103.16,54.75 105.38,54.75 | v103.48,23.32 97.13,23.32 96.49,22.68 90.78,22.68 90.14,23.32 R14.
RXD  (via drill 0.61 pad 1.02)
  Top 0.254: v109.51,75.71 109.51,80.79 110.46,81.74 111.1,81.74 111.73,82.37 111.73,83.33 110.15,84.91 110.15,94.44 v111.73,96.02
  Bottom 0.254: v109.51,75.71 109.19,75.39 104.75,75.39 104.11,74.75 81.25,74.75 79.67,73.16 78.71,73.16 | v111.73,96.02 112.05,95.71 124.43,95.71 125.07,96.34 125.07,96.98 125.7,97.61 141.26,97.61 141.9,96.98 141.9,88.72 141.26,88.09 137.13,88.09
TXD  (via drill 0.61 pad 1.02)
  Top 0.254: v78.08,95.39 77.76,95.07 77.76,88.09 78.08,87.77 78.08,86.5 77.13,85.55 77.13,72.85 76.17,71.9 76.17,70.63
  Bottom 0.254: v78.08,95.39 78.4,95.07 118.72,95.07 119.35,94.44 128.56,94.44 129.2,93.8 129.2,92.53 129.83,91.9 136.5,91.9 137.13,91.26 137.13,90.63
VCC  (via drill 0.61 pad 1.02, 0.81 pad 1.93)
  Top 0.254: v71.41,48.72 71.09,48.72
  Top 0.305: IC4. 111.42,20.46 111.42,23.32 109.51,25.22 109.51,37.61 109.83,37.92 109.83,39.19 110.46,39.83 IC3. 110.46,59.51 111.42,60.47 111.42,63 110.46,63.96 110.46,72.85 v110.46,78.88 | 134.59,80.47 IC11. | 146.66,43.64 146.66,73.48 R2. 148.56,74.12 149.2,74.75 149.2,87.45 149.83,88.09 C4. | 146.66,43.64 T1. | 146.66,43.64 146.66,38.56 146.02,37.92 146.02,25.22 146.66,24.59 148.56,24.59 | 72.05,53.8 71.09,52.85 71.09,48.72 71.09,37.92 71.73,37.29 72.36,37.29 | 90.14,10.62 90.78,9.98 90.78,2.36 91.41,1.73 IC2. 99.03,1.73 99.67,2.36 99.67,10.3 99.03,10.93 99.03,28.08 IC8. 95.86,29.35 95.22,29.98 95.22,32.53 v95.22,49.99 | C11. 93,61.42 91.41,63 90.46,63.96 90.46,77.93 v91.41,78.88 IC1. | v92.68,90.31 v92.68,99.2
  Bottom 0.254: 110.78,79.2 v110.46,78.88 110.15,79.2 | v91.41,78.88 91.73,79.2
  Bottom 0.305: IC3. JP2. | 134.59,80.47 133.32,81.74 125.7,81.74 124.43,80.47 121.26,80.47 119.99,79.2 110.78,79.2 | IC11. 139.99,77.93 140.63,77.29 140.63,74.75 141.26,74.12 R2. | v95.22,49.99 C11. 91.73,48.72 v71.41,48.72 | 91.73,79.2 110.15,79.2 | v5.05,97.93 v8.23,97.93 v11.09,97.93 v13.94,97.93 v16.8,97.93 v19.66,97.93 v22.52,97.93 v25.37,97.93 v28.23,97.93 v31.09,97.93 v33.95,97.93 v36.8,97.93 v39.66,97.93 v42.52,97.93 v45.38,97.93 v48.23,97.93 v51.09,97.93 v53.95,97.93 v56.81,97.93 v59.66,97.93 72.36,97.93 73.63,99.2 v92.68,99.2 | v92.68,90.31 92.68,86.5 92.05,85.86 IC1. | U$65. C4.
VN  (via drill 0.61 pad 1.02)
  Top 0.254: 125.7,19.51 126.66,20.46 v126.66,33.16 126.66,34.11 125.7,35.07 125.7,37.29
  Bottom 0.254: v126.66,33.16 101.57,33.16 97.76,36.97
VPD  (via drill 0.61 pad 1.02)
  Top 0.254: v86.33,69.04 86.33,85.86 | v110.78,26.81 110.46,27.13 IC5. 110.46,38.24 111.42,39.19 111.42,50.3 111.1,50.62 111.1,54.11 111.73,54.75 111.73,56.34 113,57.61 113,59.51 112.05,60.47 112.05,63 113,63.96 v113,69.04 113,72.85 v113,76.66 | v156.5,25.22 156.5,12.84 154.91,11.25 154.91,1.73 154.91,1.41
  Bottom 0.254: v86.33,69.04 106.65,69.04 v113,69.04 | 124.43,77.29 125.07,76.66 126.34,76.66 126.97,76.02 IC10.8 | 90.14,27.45 92.68,27.45 93.95,26.18 95.86,26.18 96.18,26.49 110.46,26.49 v110.78,26.81 142.53,26.81 143.17,26.18 149.2,26.18 150.15,25.22 v156.5,25.22 | 124.43,77.29 123.8,76.66 v113,76.66 | 124.43,77.29 124.43,77.93
WR  (via drill 0.61 pad 1.02)
  Top 0.254: v78.08,11.89 78.08,51.26 77.76,51.57 77.76,59.19 78.71,60.15 78.71,63 77.76,63.96 77.76,66.18 78.4,66.82 79.03,66.82 79.67,67.45 79.67,71.58 79.03,72.21 78.4,72.21 77.76,72.85 77.76,83.96 78.4,84.6 79.03,84.6 79.67,85.23 v79.67,92.53 | 116.81,83.01 116.18,83.01 115.54,83.64 115.54,87.77 113.96,89.36 v113.96,92.53
  Bottom 0.254: 72.36,11.89 v78.08,11.89 | v79.67,92.53 v113.96,92.53

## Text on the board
Top: +5V | P0 | +5V | INT1 | P4 | GND | P6 | P5 | PWR | VCC | P1 | PB | PC | PA | GND | GND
